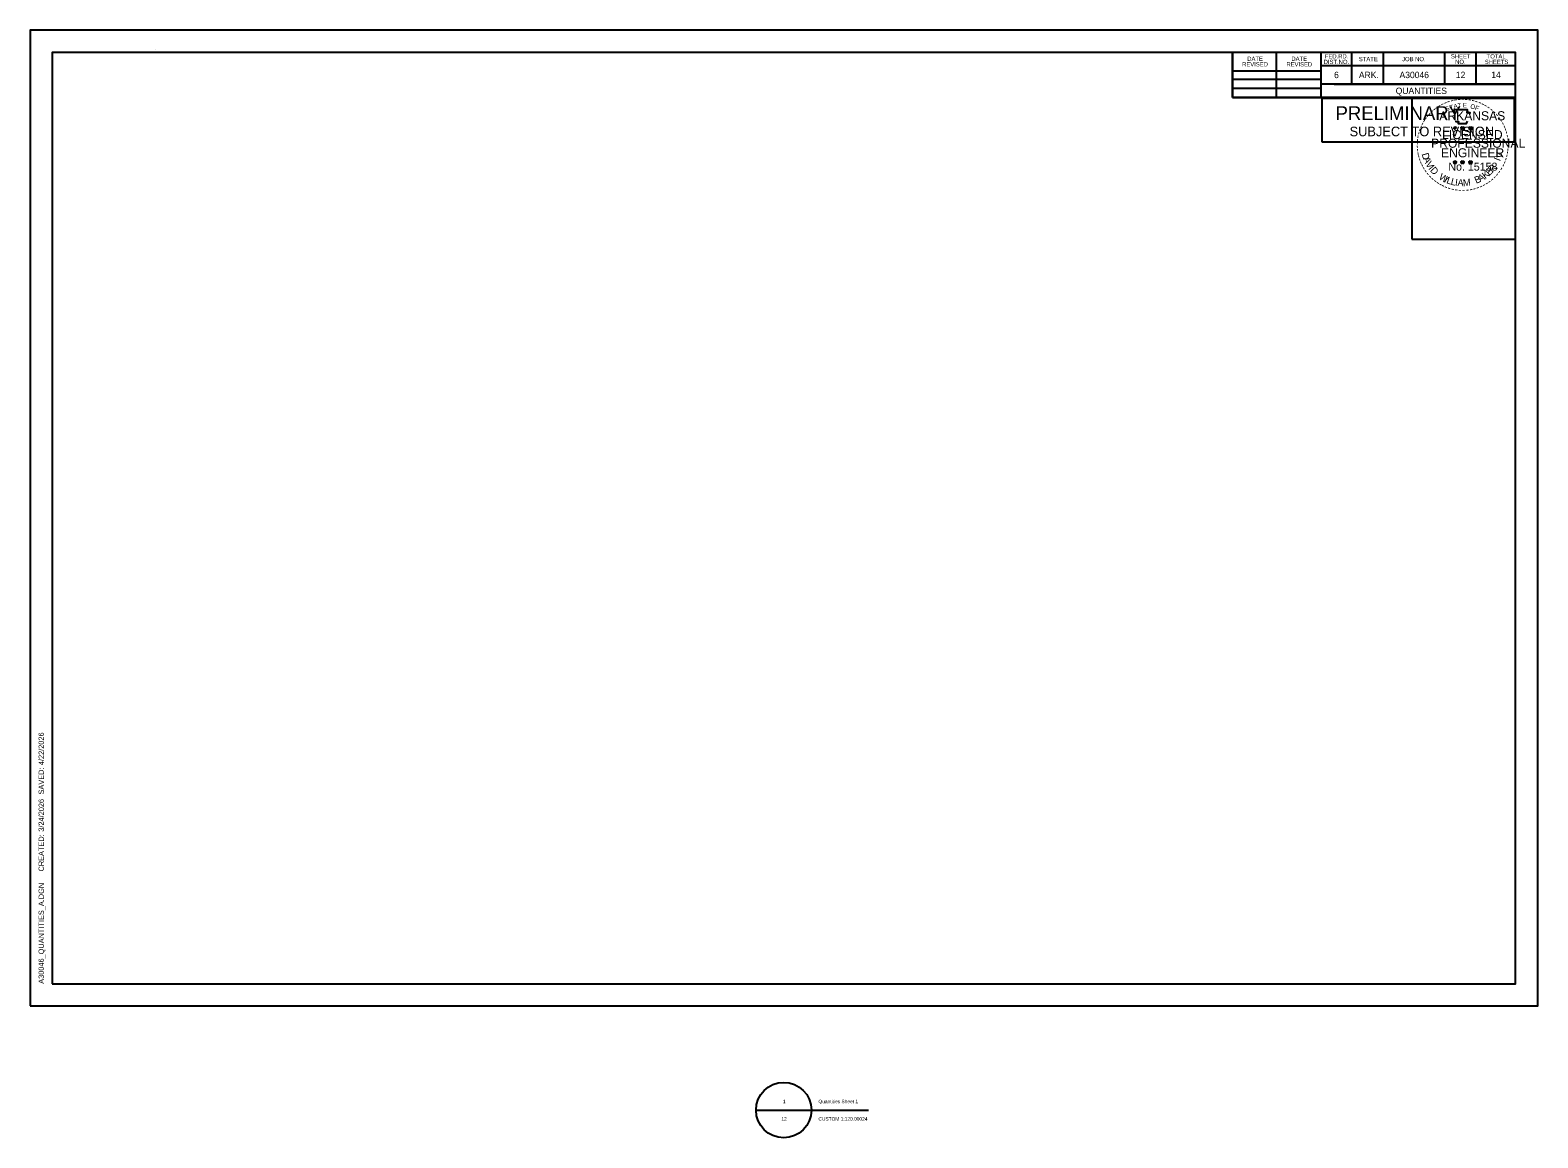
# Model space of a CAD drawing. Extents: x 0 to 1.42, y -0.12 to 0.92.
import ezdxf

# ---------------------------------------------------------------- set-up
doc = ezdxf.new("R2010")
doc.units = 0
for name, color, linetype in [('Default', 7, 'Continuous'), ('R_Border Notes', 7, 'Continuous'), ('R_Border PE', 7, 'Continuous'), ('SHET_Annotations', 7, 'Continuous'), ('SHET_Border-Lines', 7, 'Continuous'), ('SHET_Stamp-PE-Chief-Eng', 7, 'Continuous')]:
    doc.layers.add(name, color=color, linetype=linetype)

msp = doc.modelspace()

# ---------------------------------------------------------------- linework, layer by layer
at = {"layer": 'Default'}
for p, q in [((0.6821, -0.0979), (0.7341, -0.0979)), ((0.7083, -0.0979), (0.7876, -0.0979))]:
    msp.add_line(p, q, dxfattribs=at)
msp.add_circle((0.7081, -0.0979), 0.026, dxfattribs=at)
at = {"layer": 'R_Border Notes'}
for p, q in [((0.1176, 0.8988), (0.1176, 0.8988)), ((0.1176, 0.8988), (0.1176, 0.8988)), ((1.1296, 0.8534), (1.1296, 0.8958)), ((1.1711, 0.8534), (1.1711, 0.8958)), ((1.2127, 0.8958), (1.2127, 0.8534)), ((1.2417, 0.8958), (1.2417, 0.866)), ((1.2712, 0.8958), (1.2712, 0.866)), ((1.3289, 0.8958), (1.3289, 0.866)), ((1.3584, 0.8958), (1.3584, 0.866)), ((1.1296, 0.8786), (1.2127, 0.8786)), ((1.3958, 0.8832), (1.2127, 0.8832)), ((1.3958, 0.8833), (1.3958, 0.8833)), ((1.1296, 0.8706), (1.2127, 0.8706)), ((1.3958, 0.866), (1.2127, 0.866)), ((1.2252, 0.866), (1.3958, 0.866)), ((1.1296, 0.8622), (1.2127, 0.8622)), ((1.3958, 0.8534), (1.1296, 0.8534))]:
    msp.add_line(p, q, dxfattribs=at)
for points in [[(0, 0), (1.4167, 0), (1.4167, 0.9167), (0, 0.9167)], [(0.0208, 0.0208), (1.3958, 0.0208), (1.3958, 0.8958), (0.0208, 0.8958)], [(1.1296, 0.8534), (1.3958, 0.8534), (1.3958, 0.8958), (1.1296, 0.8958)]]:
    msp.add_lwpolyline(points, close=True, dxfattribs=at)
at = {"layer": 'SHET_Annotations'}
msp.add_lwpolyline([(1.2137, 0.8119), (1.3948, 0.8119), (1.3948, 0.8524), (1.2137, 0.8524)], close=True, dxfattribs=at)
at = {"layer": 'SHET_Border-Lines'}
for p, q in [((1.3373, 0.8252), (1.3388, 0.8247)), ((1.3373, 0.8252), (1.3384, 0.825)), ((1.3373, 0.8252), (1.3383, 0.8247)), ((1.3379, 0.8235), (1.3388, 0.8247)), ((1.3379, 0.8235), (1.3384, 0.8245)), ((1.3379, 0.8235), (1.3388, 0.8244)), ((1.3388, 0.8263), (1.3386, 0.8252)), ((1.3388, 0.8247), (1.3388, 0.8263)), ((1.3388, 0.8263), (1.339, 0.8252)), ((1.3403, 0.8252), (1.3388, 0.8247)), ((1.3397, 0.8235), (1.3388, 0.8247)), ((1.3397, 0.8235), (1.3388, 0.8244)), ((1.3403, 0.8252), (1.3391, 0.825)), ((1.3397, 0.8235), (1.3391, 0.8247)), ((1.3403, 0.8252), (1.3394, 0.8248)), ((1.3444, 0.8252), (1.3459, 0.8247)), ((1.3444, 0.8252), (1.3455, 0.825)), ((1.3444, 0.8252), (1.3454, 0.8247)), ((1.345, 0.8235), (1.3459, 0.8247)), ((1.345, 0.8235), (1.3455, 0.8245)), ((1.345, 0.8235), (1.3459, 0.8244)), ((1.3459, 0.8263), (1.3457, 0.8252)), ((1.3459, 0.8247), (1.3459, 0.8263)), ((1.3459, 0.8263), (1.3461, 0.8252)), ((1.3474, 0.8252), (1.3459, 0.8247)), ((1.3468, 0.8235), (1.3459, 0.8247)), ((1.3468, 0.8235), (1.3459, 0.8244)), ((1.3474, 0.8252), (1.3462, 0.825)), ((1.3468, 0.8235), (1.3462, 0.8247)), ((1.3474, 0.8252), (1.3465, 0.8248)), ((1.3519, 0.8252), (1.3534, 0.8247)), ((1.3519, 0.8252), (1.353, 0.825)), ((1.3519, 0.8252), (1.3529, 0.8246)), ((1.3525, 0.8234), (1.3534, 0.8247)), ((1.3525, 0.8234), (1.353, 0.8245)), ((1.3525, 0.8234), (1.3534, 0.8243)), ((1.3534, 0.8262), (1.3532, 0.8252)), ((1.3534, 0.8247), (1.3534, 0.8262)), ((1.3534, 0.8262), (1.3536, 0.8252)), ((1.3549, 0.8252), (1.3534, 0.8247)), ((1.3543, 0.8234), (1.3534, 0.8247)), ((1.3543, 0.8234), (1.3534, 0.8243)), ((1.3549, 0.8252), (1.3537, 0.825)), ((1.3543, 0.8234), (1.3537, 0.8247)), ((1.3549, 0.8252), (1.354, 0.8247)), ((1.3388, 0.7941), (1.3386, 0.793)), ((1.3388, 0.7926), (1.3388, 0.7941)), ((1.3388, 0.7941), (1.339, 0.793)), ((1.3459, 0.7941), (1.3457, 0.793)), ((1.3459, 0.7926), (1.3459, 0.7941)), ((1.3459, 0.7941), (1.3461, 0.793)), ((1.3534, 0.7941), (1.3532, 0.793)), ((1.3534, 0.7925), (1.3534, 0.7941)), ((1.3534, 0.7941), (1.3536, 0.793)), ((1.3373, 0.793), (1.3388, 0.7926)), ((1.3373, 0.793), (1.3384, 0.7928)), ((1.3373, 0.793), (1.3383, 0.7925)), ((1.3379, 0.7913), (1.3388, 0.7926)), ((1.3379, 0.7913), (1.3384, 0.7923)), ((1.3379, 0.7913), (1.3388, 0.7922)), ((1.3403, 0.793), (1.3388, 0.7926)), ((1.3397, 0.7913), (1.3388, 0.7926)), ((1.3397, 0.7913), (1.3388, 0.7922)), ((1.3403, 0.793), (1.3391, 0.7928)), ((1.3397, 0.7913), (1.3391, 0.7925)), ((1.3403, 0.793), (1.3394, 0.7926)), ((1.3444, 0.793), (1.3459, 0.7926)), ((1.3444, 0.793), (1.3455, 0.7928)), ((1.3444, 0.793), (1.3454, 0.7925)), ((1.345, 0.7913), (1.3459, 0.7926)), ((1.345, 0.7913), (1.3455, 0.7923)), ((1.345, 0.7913), (1.3459, 0.7922)), ((1.3474, 0.793), (1.3459, 0.7926)), ((1.3468, 0.7913), (1.3459, 0.7926)), ((1.3468, 0.7913), (1.3459, 0.7922)), ((1.3474, 0.793), (1.3461, 0.7928)), ((1.3468, 0.7913), (1.3462, 0.7925)), ((1.3474, 0.793), (1.3465, 0.7926)), ((1.3519, 0.793), (1.3534, 0.7925)), ((1.3519, 0.793), (1.353, 0.7928)), ((1.3519, 0.793), (1.3529, 0.7925)), ((1.3525, 0.7912), (1.3534, 0.7925)), ((1.3525, 0.7912), (1.353, 0.7923)), ((1.3525, 0.7912), (1.3534, 0.7922)), ((1.3549, 0.793), (1.3534, 0.7925)), ((1.3543, 0.7912), (1.3534, 0.7925)), ((1.3543, 0.7912), (1.3534, 0.7922)), ((1.3549, 0.793), (1.3537, 0.7928)), ((1.3543, 0.7912), (1.3537, 0.7925)), ((1.3549, 0.793), (1.354, 0.7926))]:
    msp.add_line(p, q, dxfattribs=at)
msp.add_lwpolyline([(1.2983, 0.7203), (1.3958, 0.7203), (1.3958, 0.8534), (1.2983, 0.8534)], close=True, dxfattribs=at)
for points in [[(1.3375, 0.8417), (1.3386, 0.8382)], [(1.3524, 0.8378), (1.353, 0.839), (1.3501, 0.8389), (1.3507, 0.8417), (1.3375, 0.8417)], [(1.3396, 0.8314), (1.3396, 0.831), (1.342, 0.8309), (1.3418, 0.8289), (1.3497, 0.8289), (1.3506, 0.8312)], [(1.3459, 0.8263), (1.3468, 0.8235), (1.3444, 0.8252), (1.3474, 0.8252), (1.345, 0.8235), (1.3459, 0.8263)], [(1.3534, 0.8262), (1.3543, 0.8234), (1.3519, 0.8252), (1.3549, 0.8252), (1.3525, 0.8234), (1.3534, 0.8262)], [(1.3388, 0.7941), (1.3397, 0.7913), (1.3373, 0.793), (1.3403, 0.793), (1.3379, 0.7913), (1.3388, 0.7941)], [(1.3459, 0.7941), (1.3468, 0.7913), (1.3444, 0.793), (1.3474, 0.793), (1.345, 0.7913), (1.3459, 0.7941)], [(1.3534, 0.7941), (1.3543, 0.7912), (1.3519, 0.793), (1.3549, 0.793), (1.3525, 0.7912), (1.3534, 0.7941)]]:
    msp.add_lwpolyline(points, dxfattribs=at)
for centre, radius in [((1.3388, 0.8247), 0.000732), ((1.3388, 0.8247), 0.000614), ((1.3388, 0.8247), 0.000492), ((1.3388, 0.8247), 0.000421), ((1.3388, 0.8247), 0.000318), ((1.3388, 0.8247), 0.000211), ((1.3388, 0.8247), 0.000126), ((1.3459, 0.8247), 0.000732), ((1.3459, 0.8247), 0.000614), ((1.3459, 0.8247), 0.000492), ((1.3459, 0.8247), 0.000421), ((1.3459, 0.8247), 0.000318), ((1.3459, 0.8247), 0.000211), ((1.3459, 0.8247), 0.000126), ((1.3534, 0.8247), 0.000732), ((1.3534, 0.8247), 0.000614), ((1.3534, 0.8247), 0.000492), ((1.3534, 0.8247), 0.000421), ((1.3534, 0.8247), 0.000318), ((1.3534, 0.8247), 0.000211), ((1.3534, 0.8247), 0.000126), ((1.3388, 0.7926), 0.000732), ((1.3388, 0.7926), 0.000614), ((1.3388, 0.7926), 0.000492), ((1.3388, 0.7926), 0.000421), ((1.3388, 0.7926), 0.000318), ((1.3388, 0.7926), 0.000211), ((1.3388, 0.7926), 0.000126), ((1.3459, 0.7926), 0.000732), ((1.3459, 0.7926), 0.000614), ((1.3459, 0.7926), 0.000492), ((1.3459, 0.7926), 0.000421), ((1.3459, 0.7926), 0.000318), ((1.3459, 0.7926), 0.000211), ((1.3459, 0.7926), 0.000126), ((1.3534, 0.7925), 0.000732), ((1.3534, 0.7925), 0.000614), ((1.3534, 0.7925), 0.000492), ((1.3534, 0.7925), 0.000421), ((1.3534, 0.7925), 0.000318), ((1.3534, 0.7925), 0.000211), ((1.3534, 0.7925), 0.000126)]:
    msp.add_circle(centre, radius, dxfattribs=at)

# ---------------------------------------------------------------- texts
at = {"layer": 'Default'}
for s, height, p in [('1', 0.00328, (0.7073, -0.0914)), ('Quantities Sheet 1', 0.003281, (0.7407, -0.0914)), ('12', 0.00328, (0.7059, -0.1078)), ('CUSTOM 1:120.00024', 0.003281, (0.7407, -0.1078))]:
    msp.add_text(s, height=height, dxfattribs=at).set_placement(p)
at = {"layer": 'R_Border PE'}
for s, p in [('6', (1.2252, 0.8716)), ('ARK.', (1.2485, 0.8716)), ('A30046', (1.2867, 0.8716)), ('12', (1.3396, 0.8716)), ('14', (1.3729, 0.8717)), ('QUANTITIES', (1.2831, 0.8567))]:
    msp.add_text(s, height=0.006, dxfattribs=at).set_placement(p)
at = {"layer": 'SHET_Annotations'}
for s, height, p in [('PRELIMINARY', 0.013, (1.2266, 0.8322)), ('SUBJECT TO REVISION', 0.009, (1.2398, 0.817))]:
    msp.add_text(s, height=height, dxfattribs=at).set_placement(p)
at = {"layer": 'SHET_Border-Lines'}
for s, height, rotation, p in [('-', 0.0068, 19.1761, (1.3322, 0.8465)), ('-', 0.0068, 13.6302, (1.3354, 0.8475)), ('-', 0.0068, 10.2193, (1.3383, 0.8482)), ('-', 0.0068, 5.8968, (1.3414, 0.8487)), ('-', 0.0068, 0.1862, (1.3446, 0.849)), ('-', 0.0068, 357.743, (1.3477, 0.8489)), ('-', 0.0068, 352.1617, (1.3509, 0.8487)), ('-', 0.0068, 347.2049, (1.3539, 0.8482)), ('-', 0.0068, 342.3362, (1.3566, 0.8475)), ('-', 0.0068, 50.6142, (1.3143, 0.8333)), ('-', 0.0068, 48.4231, (1.316, 0.8353)), ('-', 0.0068, 42.9622, (1.3179, 0.8374)), ('-', 0.0068, 38.9507, (1.3198, 0.8391)), ('-', 0.0068, 36.2317, (1.3218, 0.8407)), ('-', 0.0068, 34.0636, (1.3243, 0.8424)), ('-', 0.0068, 28.7918, (1.3268, 0.844)), ('-', 0.0068, 24.3072, (1.3295, 0.8453)), ('S', 0.00425, 21.594, (1.3305, 0.8403)), ('T', 0.00425, 16.4036, (1.3344, 0.8417)), ('A', 0.00425, 11.2132, (1.3379, 0.8428)), ('T', 0.00425, 6.0228, (1.3415, 0.8435)), ('E', 0.00425, 0.8323, (1.3462, 0.844)), ('O', 0.00425, 350.4515, (1.353, 0.8431)), ('F', 0.00425, 340.0707, (1.3571, 0.8421)), ('-', 0.0068, 337.8551, (1.3597, 0.8466)), ('-', 0.0068, 334.1211, (1.3624, 0.8454)), ('-', 0.0068, 329.6409, (1.3649, 0.8442)), ('-', 0.0068, 325.8627, (1.3676, 0.8427)), ('-', 0.0068, 320.5297, (1.3702, 0.8409)), ('-', 0.0068, 315.5786, (1.3728, 0.8388)), ('-', 0.0068, 309.8797, (1.3752, 0.8365)), ('-', 0.0068, 72.3945, (1.3078, 0.8207)), ('-', 0.0068, 67.7743, (1.3088, 0.8234)), ('-', 0.0068, 62.8713, (1.3099, 0.826)), ('-', 0.0068, 58.0706, (1.3112, 0.8286)), ('-', 0.0068, 54.2325, (1.3126, 0.8309)), ('-', 0.0068, 306.6522, (1.3774, 0.8339)), ('-', 0.00595, 303.6753, (1.3795, 0.8315)), ('-', 0.0068, 299.6684, (1.3808, 0.8289)), ('-', 0.0068, 294.6628, (1.3822, 0.8263)), ('-', 0.0068, 290.5728, (1.3833, 0.8239)), ('-', 0.0068, 285.1233, (1.3843, 0.8214)), ('-', 0.0068, 89.0622, (1.306, 0.8088)), ('-', 0.0068, 94.1959, (1.3061, 0.8057)), ('-', 0.0068, 85.1863, (1.3061, 0.8117)), ('-', 0.0068, 81.2013, (1.3064, 0.8147)), ('-', 0.0068, 75.461, (1.307, 0.8177)), ('-', 0.0068, 280.5493, (1.3851, 0.8182)), ('-', 0.0068, 276.5962, (1.3858, 0.815)), ('-', 0.0068, 274.3301, (1.3861, 0.8119)), ('-', 0.0068, 269.9407, (1.3862, 0.8092)), ('-', 0.0068, 98.9479, (1.3065, 0.8028)), ('-', 0.0068, 101.7149, (1.307, 0.7997)), ('-', 0.0068, 105.4578, (1.3077, 0.7972)), ('-', 0.0068, 109.0874, (1.3086, 0.7945)), ('-', 0.0068, 114.0643, (1.3097, 0.792)), ('D', 0.00654, 286.2848, (1.3074, 0.8003)), ('A', 0.00654, 292.7835, (1.3086, 0.796)), ('V', 0.00654, 300.7936, (1.3108, 0.791)), ('I', 0.00654, 69.0301, (1.3812, 0.7931)), ('V', 0.00654, 72.6573, (1.3822, 0.7954)), ('-', 0.0068, 247.8887, (1.3837, 0.7948)), ('-', 0.0068, 252.8681, (1.3846, 0.7977)), ('-', 0.0068, 255.7626, (1.3854, 0.8007)), ('-', 0.0068, 260.9953, (1.3858, 0.8036)), ('-', 0.0068, 263.5172, (1.3861, 0.8064)), ('-', 0.0068, 115.7289, (1.311, 0.7894)), ('-', 0.0068, 120.4471, (1.3125, 0.7869)), ('-', 0.0068, 125.8934, (1.3142, 0.7845)), ('-', 0.0068, 130.7181, (1.3162, 0.7821)), ('I', 0.00654, 308.3502, (1.3135, 0.7866)), ('-', 0.0068, 134.2238, (1.3184, 0.7798)), ('D', 0.00654, 311.9774, (1.315, 0.7847)), ('W', 0.00654, 328.0731, (1.323, 0.7771)), ('I', 0.00654, 336.6877, (1.328, 0.7741)), ('B', 0.00654, 22.8589, (1.3587, 0.7723)), ('A', 0.00654, 28.9042, (1.3625, 0.7739)), ('K', 0.00654, 36.9143, (1.3672, 0.7766)), ('E', 0.00654, 44.0175, (1.3711, 0.7795)), ('R', 0.00654, 50.3651, (1.3742, 0.7825)), ('-', 0.0068, 225.7653, (1.3753, 0.7814)), (',', 0.00654, 57.4684, (1.3773, 0.7863)), ('-', 0.0068, 231.2538, (1.3773, 0.7838)), ('-', 0.0068, 233.8452, (1.3792, 0.7862)), ('-', 0.0068, 239.0712, (1.3809, 0.789)), ('-', 0.0068, 244.6197, (1.3825, 0.7921)), ('-', 0.0068, 138.9338, (1.3206, 0.7778)), ('-', 0.0068, 144.6463, (1.323, 0.7761)), ('-', 0.0068, 148.0898, (1.3254, 0.7745)), ('-', 0.0068, 151.5704, (1.3278, 0.7732)), ('-', 0.0068, 154.6002, (1.3301, 0.7721)), ('-', 0.0068, 158.5612, (1.3327, 0.771)), ('L', 0.00654, 340.3149, (1.3303, 0.7731)), ('-', 0.0068, 162.7983, (1.3356, 0.7701)), ('L', 0.00654, 346.6625, (1.3344, 0.7716)), ('-', 0.0068, 167.5555, (1.3387, 0.7694)), ('-', 0.0068, 173.1155, (1.3419, 0.769)), ('I', 0.00654, 353.0101, (1.3386, 0.7706)), ('A', 0.00654, 356.6373, (1.341, 0.7703)), ('-', 0.0068, 176.5183, (1.3451, 0.7687)), ('-', 0.0068, 181.5918, (1.3483, 0.7688)), ('M', 0.00654, 4.6473, (1.3465, 0.77)), ('-', 0.0068, 185.8167, (1.3517, 0.7691)), ('-', 0.0068, 191.2858, (1.3549, 0.7697)), ('-', 0.0068, 195.4743, (1.358, 0.7705)), ('-', 0.0068, 199.4643, (1.3608, 0.7716)), ('-', 0.0068, 204.2516, (1.3635, 0.7727)), ('-', 0.0068, 207.3568, (1.3661, 0.7741)), ('-', 0.0068, 212.2491, (1.3685, 0.7756)), ('-', 0.0068, 215.7363, (1.3708, 0.7772)), ('-', 0.0068, 221.0851, (1.3731, 0.7792))]:
    msp.add_text(s, height=height, rotation=rotation, dxfattribs=at).set_placement(p)
for s, height, p in [('ARKANSAS', 0.0085, (1.3241, 0.832)), ('LICENSED', 0.0085, (1.3267, 0.8143)), ('PROFESSIONAL', 0.0085, (1.3164, 0.8062)), ('ENGINEER', 0.0085, (1.3257, 0.7972)), ('No. 15158', 0.00747, (1.3326, 0.7847)), ('AAMU', 0.000000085, (1.3456, 0.77))]:
    msp.add_text(s, height=height, dxfattribs=at).set_placement(p)
at = {"layer": 'SHET_Stamp-PE-Chief-Eng'}
for s, p in [('FED.RD.', (1.2165, 0.8901)), ('SHEET', (1.335, 0.8901)), ('TOTAL', (1.3686, 0.8901)), ('REVISED', (1.1388, 0.8826)), ('DATE', (1.1436, 0.8878)), ('REVISED', (1.1804, 0.8826)), ('DATE', (1.1851, 0.8878)), ('DIST.NO.', (1.2154, 0.8849)), ('STATE', (1.2485, 0.8875)), ('JOB NO.', (1.2891, 0.8875)), ('NO.', (1.339, 0.8849)), ('SHEETS', (1.3668, 0.8849))]:
    msp.add_text(s, height=0.004, dxfattribs=at).set_placement(p)
for s, p in [('4/22/2026', (0.0129, 0.2262)), ('  SAVED: ', (0.0129, 0.1948)), ('3/24/2026', (0.0129, 0.1637)), ('     CREATED: ', (0.0129, 0.1167)), ('A30046_QUANTITIES_A.DGN', (0.0129, 0.0208))]:
    msp.add_text(s, height=0.005, rotation=90, dxfattribs=at).set_placement(p)

doc.saveas('drawing.dxf')
